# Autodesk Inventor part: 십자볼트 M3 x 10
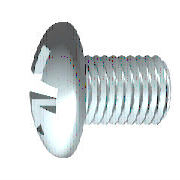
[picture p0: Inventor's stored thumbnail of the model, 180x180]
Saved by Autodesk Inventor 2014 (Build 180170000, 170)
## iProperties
IsCustomPart: 0
Created: 2012-02
Part Number: 십자볼트 M3 x 10
Material: 스테인리스강
Description: 십자 오목 머리 나사
Document SubType Name: Modeling
Standard: KS B 1023
Designer: mduedu
Standards Organization: KS
Language: ko-KR
Size Designation: A  M 3 x 10 - H
Categories: <MemberInstance><Categories><Category DisplayName="조임쇠" InternalName="e4da775c-781d-43d5-af7c-5136215cf5a6" Mnemonic="FSTN"><Category DisplayName="볼트" InternalN
Density: 1 g/cm^3
Appearance: 반광택
Author: mduedu
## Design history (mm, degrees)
workplane "Work Plane3"
sketch "스케치2"
  geometry: L1 (-3.72, 0)-(3.72, 0) reference; L2 (0, -3.72)-(0, 3.72) reference; L3 (0, 1.5)-(0, 0); L4 (0, 0)-(1.5, 0); L5 (0, 0)-(1.879, 1.879); L6 (0.253, 1.479)-(0.261, 0.456); L7 (1.479, 0.253)-(0.456, 0.261); L8 (0.253, -1.479)-(0.261, -0.456); L9 (1.479, -0.253)-(0.456, -0.261); L10 (-0.253, 1.479)-(-0.261, 0.456); L11 (-1.479, 0.253)-(-0.456, 0.261); L12 (-1.479, -0.253)-(-0.456, -0.261); L13 (-0.253, -1.479)-(-0.261, -0.456); A1 r 0.45 centre (0, 0) between (0.45, 0) and (0, 0.45); A2 r 1.5 centre (0, 0) between (1.5, 0) and (1.479, 0.253); A3 r 1.5 centre (0, 0) between (0.253, 1.479) and (0, 1.5); A4 r 1.5 centre (0, 0) between (1.479, 0.253) and (0.253, 1.479); A5 r 1.5 centre (0, 0) between (0, -1.5) and (0.253, -1.479); A6 r 1.5 centre (0, 0) between (0.253, -1.479) and (1.479, -0.253); A7 r 1.5 centre (0, 0) between (1.479, -0.253) and (1.5, 0); A8 r 1.5 centre (0, 0) between (-1.479, 0.253) and (-1.5, 0); A9 r 1.5 centre (0, 0) between (-0.253, 1.479) and (-1.479, 0.253); A10 r 1.5 centre (0, 0) between (0, 1.5) and (-0.253, 1.479); A11 r 1.5 centre (0, 0) between (-1.5, 0) and (-1.479, -0.253); A12 r 1.5 centre (0, 0) between (-1.479, -0.253) and (-0.253, -1.479); A13 r 1.5 centre (0, 0) between (-0.253, -1.479) and (0, -1.5); A14 r 0.525 centre (0, 0) between (0.525, 0) and (0, 0.525); A15 r 0.197 centre (0.457, 0.457) between (0.261, 0.456) and (0.456, 0.261); A16 r 0.197 centre (0.457, -0.457) between (0.456, -0.261) and (0.261, -0.456); A17 r 0.197 centre (-0.457, 0.457) between (-0.456, 0.261) and (-0.261, 0.456); A18 r 0.197 centre (-0.457, -0.457) between (-0.261, -0.456) and (-0.456, -0.261); 1 further point
  constraints: 38 point on circle, 22 end point, 19 symmetric about line, 18 centre point, 4 coincident, 3 collinear, 3 point on line, 3 tangent, 1 perpendicular, 21 other
  dimensions: "d4" = 45 deg angle of L5 L4; "d5" = 0.9 diameter of A1 (= 0.3 x SDM); "d6" = 3 diameter of A4 (= SDM); "d7" = 0.2525 distance from line of L6.start L3 (= 0.5 x SBR); "d14" = 1.05 diameter of A14 (= 0.35 x SDM)
extrude "슬롯" join sketch "스케치2" taper "d15" = 5 deg; stored distance "d54" = 10
revolve "절단부" stored, may be unused: angle "d56" = 90 deg
revolve "본체" stored, may be unused: angle "d18" = 90 deg
workplane "Work Plane1"
body "Solid1"
sketch "스케치1"
  geometry: L1 (10, 0)-(10, 1.5); L2 (10, 1.5)-(1, 1.5); L3 (3.962, 5.08)-(3.962, 5.08); L4 (-2.4, 0)-(-2.4, 2.59); L5 (-2.2, 1.4)-(-1.036, 0.82); L6 (-1.036, 0.82)-(-0.6, 0); L7 (-0.6, 0)-(10, 0); L8 (-5.105, 0)-(12.517, 0) reference; L9 (0, -1.016)-(0, 6.096) reference; L10 (-2.2, 1.4)-(-2.4, 1.5); L11 (-1.636, 2.657)-(-2.4, 2.59); L12 (-1.636, 2.657)-(0, 2.8); L13 (0, 2.8)-(0, 1.347); L14 (0, 1.347)-(0.693, 1.347); L15 (0.693, 1.347)-(1, 1.5); L16 (1, 1.5)-(0, 1.5); A1 r 5 centre (2.6, 0) between (-1.636, 2.657) and (-2.4, 0)
  constraints: 28 end point, 5 point on line, 4 collinear, 4 point on circle, 3 parallel, 2 perpendicular, 1 centre point, 1 horizontal, 1 tangent
  dimensions: "d1" = 3 diameter of L2 L7 (= GD); "d2" = 1.8 distance from line of L6.end L4 (= STI); "d11" = 3 diameter of L10.end L7 (= SDM); "d12" = 62 deg angle of L6 L7; "d13" = 26.5 deg angle of L5 L7; "d17" = 5.6 diameter of L12.end L7 (= KOD); "d19" = 5 deg angle of L12 L7 (= KEWI); "d20" = 2.4 distance between parallel lines of L4 L13 (= KOH); "d21" = 5 radius of A1 (= KR); "d23" = 2.6935 diameter of L14 L7 (= BDM); "d24" = 9 distance of L1.end L2.end (= GEL); "d25" = 0.30673 horizontal distance of L14.end L2.end (= GAL); "d28" = 10 distance between parallel lines of L1 L13 (= NLG)
fillet "모깎기1" dims "d29" = 1.2 (= RR)
fillet "모깎기2" dims "d16" = 0.101 (= 0.2 x SBR)
feature "스레드" dims "d8" = 9 (= GEL), "d9" = 0
chamfer "모따기1" distance "d26" = 0.30673 (= -0.5 x SPD + 0.5 x GD); stored, may be unused: second distance "d27" = 0.30683 (computed from GUL), angle "d78" = 45 deg
other parameters: "GD" = 3 (= NND) [user parameter; used in 2 equation terms], "NLG" = 10 [user parameter; used in 1 equation term], "GEL" = 9 [user parameter; used in 2 equation terms], "KOD" = 5.6 [user parameter; used in 1 equation term], "KOH" = 2.4 [user parameter; used in 2 equation terms], "SDM" = 3 [user parameter; used in 4 equation terms], "STI" = 1.8 [user parameter; used in 1 equation term], "SBR" = 0.505 [user parameter; used in 2 equation terms], "GAL" = 0.30673 (= 0.61345 x PTC) [user parameter; used in 1 equation term], "SPD" = 2.38655 (= NND - 1.2269 x PTC) [user parameter; used in 1 equation term], "KEWI" = 5 deg [user parameter; used in 1 equation term], "d3" = -2.4 (= -KOH), "d10" = 0, "KR" = 5 [user parameter; used in 1 equation term], "BDM" = 2.6935 [user parameter; used in 1 equation term], "GUL" = 0.30673 (= 0.61345 x PTC) [user parameter; used in 1 equation term], "RR" = 1.2 [user parameter; used in 1 equation term], "d79" = 0, "d80" = 0, "PTC" = 0.5 [user parameter; used in 5 equation terms], "THREADDIA" = 3 [user parameter; used in 1 equation term], "TOA" = 30 deg [user parameter], "NND" = 3 [user parameter; used in 2 equation terms], "GD1" = 2.38655 (= THREADDIA - 1.2269 x PTC) [user parameter]
